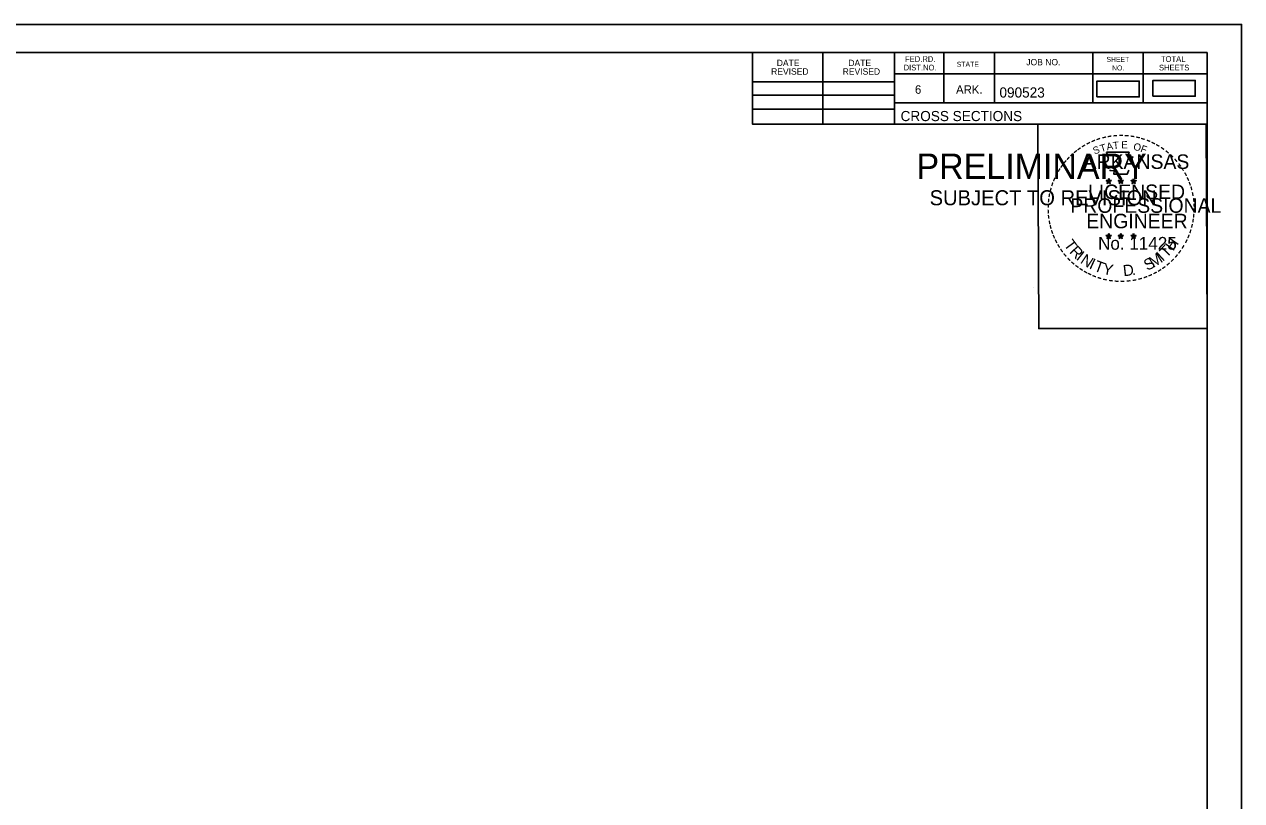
# Model space of a CAD drawing. Extents: x 1406028 to 1412453, y 321733 to 325986.
# Drawn here: x 1412285.4 to 1412453.2, y 322598 to 322705 of the extents above; entities that cross this region are included whole.
import ezdxf

# ---------------------------------------------------------------- set-up
doc = ezdxf.new("R2010")
doc.units = 0
for name, color, linetype in [('R_Alt Surface', 7, 'Continuous'), ('R_Border', 7, 'Continuous'), ('R_Border PE', 7, 'Continuous'), ('R_Border Prem', 7, 'Continuous'), ('R_Fin Surface', 7, 'Continuous'), ('R_No Plot', 7, 'Continuous')]:
    doc.layers.add(name, color=color, linetype=linetype)

msp = doc.modelspace()

# ---------------------------------------------------------------- linework, layer by layer
at = {"layer": 'R_Alt Surface'}
msp.add_lwpolyline([(1412433.22, 322695.04), (1412439.06, 322695.04), (1412439.06, 322697.23), (1412433.22, 322697.23)], close=True, dxfattribs=at)
at = {"layer": 'R_Border'}
for p, q in [((1412132.23, 322701.15), (1412448.41, 322701.15)), ((1412385.77, 322691.27), (1412385.77, 322701.15)), ((1412395.45, 322691.27), (1412395.45, 322701.15)), ((1412405.31, 322701.15), (1412405.31, 322691.27)), ((1412412.15, 322701.15), (1412412.15, 322694.21)), ((1412419.09, 322701.15), (1412419.09, 322694.21)), ((1412432.67, 322701.15), (1412432.67, 322694.21)), ((1412439.61, 322701.15), (1412439.61, 322694.21)), ((1412448.41, 322495.69), (1412448.41, 322701.15)), ((1412448.41, 322698.21), (1412405.31, 322698.21)), ((1412448.41, 322698.23), (1412448.41, 322698.23)), ((1412385.77, 322697.13), (1412405.31, 322697.13)), ((1412385.77, 322695.27), (1412405.31, 322695.27)), ((1412448.41, 322694.21), (1412405.31, 322694.21)), ((1412408.27, 322694.21), (1412448.41, 322694.21)), ((1412385.77, 322693.33), (1412405.31, 322693.33)), ((1412448.41, 322691.27), (1412385.77, 322691.27))]:
    msp.add_line(p, q, dxfattribs=at)
at = {"layer": 'R_Border PE'}
for p, q in [((1412434.5, 322683.52), (1412434.84, 322683.41)), ((1412434.5, 322683.52), (1412434.75, 322683.48)), ((1412434.5, 322683.52), (1412434.73, 322683.4)), ((1412434.63, 322683.11), (1412434.84, 322683.41)), ((1412434.63, 322683.11), (1412434.75, 322683.36)), ((1412434.63, 322683.11), (1412434.84, 322683.33)), ((1412434.84, 322683.77), (1412434.8, 322683.52)), ((1412434.84, 322683.41), (1412434.84, 322683.77)), ((1412434.84, 322683.77), (1412434.89, 322683.52)), ((1412435.19, 322683.52), (1412434.84, 322683.41)), ((1412435.06, 322683.11), (1412434.84, 322683.41)), ((1412435.06, 322683.11), (1412434.84, 322683.33)), ((1412435.19, 322683.52), (1412434.91, 322683.47)), ((1412435.06, 322683.11), (1412434.92, 322683.4)), ((1412435.19, 322683.52), (1412434.99, 322683.42)), ((1412436.17, 322683.52), (1412436.51, 322683.41)), ((1412436.17, 322683.52), (1412436.42, 322683.48)), ((1412436.17, 322683.52), (1412436.4, 322683.4)), ((1412436.3, 322683.11), (1412436.51, 322683.41)), ((1412436.3, 322683.11), (1412436.42, 322683.36)), ((1412436.3, 322683.11), (1412436.51, 322683.33)), ((1412436.51, 322683.77), (1412436.47, 322683.52)), ((1412436.51, 322683.41), (1412436.51, 322683.77)), ((1412436.51, 322683.77), (1412436.56, 322683.52)), ((1412436.86, 322683.52), (1412436.51, 322683.41)), ((1412436.73, 322683.11), (1412436.51, 322683.41)), ((1412436.73, 322683.11), (1412436.51, 322683.33)), ((1412436.86, 322683.52), (1412436.58, 322683.47)), ((1412436.73, 322683.11), (1412436.59, 322683.4)), ((1412436.86, 322683.52), (1412436.66, 322683.42)), ((1412437.93, 322683.51), (1412438.28, 322683.4)), ((1412437.93, 322683.51), (1412438.18, 322683.46)), ((1412437.93, 322683.51), (1412438.17, 322683.39)), ((1412438.06, 322683.1), (1412438.28, 322683.4)), ((1412438.06, 322683.1), (1412438.19, 322683.34)), ((1412438.06, 322683.1), (1412438.28, 322683.32)), ((1412438.28, 322683.76), (1412438.24, 322683.51)), ((1412438.28, 322683.4), (1412438.28, 322683.76)), ((1412438.28, 322683.76), (1412438.33, 322683.51)), ((1412438.63, 322683.51), (1412438.28, 322683.4)), ((1412438.49, 322683.1), (1412438.28, 322683.4)), ((1412438.49, 322683.1), (1412438.28, 322683.31)), ((1412438.63, 322683.51), (1412438.34, 322683.46)), ((1412438.49, 322683.1), (1412438.35, 322683.39)), ((1412438.63, 322683.51), (1412438.42, 322683.41)), ((1412434.49, 322675.95), (1412434.84, 322675.84)), ((1412434.49, 322675.95), (1412434.74, 322675.9)), ((1412434.49, 322675.95), (1412434.73, 322675.83)), ((1412434.62, 322675.54), (1412434.84, 322675.84)), ((1412434.62, 322675.54), (1412434.75, 322675.78)), ((1412434.62, 322675.54), (1412434.84, 322675.76)), ((1412434.84, 322676.2), (1412434.8, 322675.95)), ((1412434.84, 322675.84), (1412434.84, 322676.2)), ((1412434.84, 322676.2), (1412434.89, 322675.95)), ((1412435.19, 322675.95), (1412434.84, 322675.84)), ((1412435.05, 322675.54), (1412434.84, 322675.84)), ((1412435.05, 322675.54), (1412434.84, 322675.75)), ((1412435.19, 322675.95), (1412434.9, 322675.9)), ((1412435.05, 322675.54), (1412434.92, 322675.83)), ((1412435.19, 322675.95), (1412434.98, 322675.85)), ((1412436.16, 322675.95), (1412436.51, 322675.84)), ((1412436.16, 322675.95), (1412436.41, 322675.9)), ((1412436.16, 322675.95), (1412436.4, 322675.83)), ((1412436.29, 322675.54), (1412436.51, 322675.84)), ((1412436.29, 322675.54), (1412436.42, 322675.78)), ((1412436.29, 322675.54), (1412436.51, 322675.76)), ((1412436.51, 322676.2), (1412436.47, 322675.95)), ((1412436.51, 322675.84), (1412436.51, 322676.2)), ((1412436.51, 322676.2), (1412436.56, 322675.95)), ((1412436.86, 322675.95), (1412436.51, 322675.84)), ((1412436.72, 322675.54), (1412436.51, 322675.84)), ((1412436.72, 322675.54), (1412436.51, 322675.75)), ((1412436.86, 322675.95), (1412436.57, 322675.9)), ((1412436.72, 322675.54), (1412436.59, 322675.83)), ((1412436.86, 322675.95), (1412436.65, 322675.85)), ((1412437.93, 322675.94), (1412438.28, 322675.83)), ((1412437.93, 322675.94), (1412438.18, 322675.89)), ((1412437.93, 322675.94), (1412438.16, 322675.82)), ((1412438.06, 322675.53), (1412438.28, 322675.83)), ((1412438.06, 322675.53), (1412438.19, 322675.77)), ((1412438.06, 322675.53), (1412438.27, 322675.75)), ((1412438.28, 322676.19), (1412438.24, 322675.94)), ((1412438.49, 322675.53), (1412438.27, 322675.74)), ((1412438.28, 322675.83), (1412438.28, 322676.19)), ((1412438.28, 322676.19), (1412438.33, 322675.94)), ((1412438.62, 322675.94), (1412438.28, 322675.83)), ((1412438.49, 322675.53), (1412438.28, 322675.83)), ((1412438.62, 322675.94), (1412438.34, 322675.89)), ((1412438.49, 322675.53), (1412438.35, 322675.82)), ((1412438.62, 322675.94), (1412438.42, 322675.84))]:
    msp.add_line(p, q, dxfattribs=at)
for points in [[(1412434.54, 322687.4), (1412434.81, 322686.57)], [(1412438.05, 322686.48), (1412438.19, 322686.76), (1412437.5, 322686.74), (1412437.65, 322687.4), (1412434.54, 322687.4)], [(1412435.03, 322684.98), (1412435.03, 322684.89), (1412435.59, 322684.87), (1412435.54, 322684.4), (1412437.41, 322684.4), (1412437.61, 322684.93)], [(1412434.84, 322683.77), (1412435.06, 322683.11), (1412434.5, 322683.52), (1412435.19, 322683.52), (1412434.63, 322683.11), (1412434.84, 322683.77)], [(1412436.51, 322683.77), (1412436.73, 322683.11), (1412436.17, 322683.52), (1412436.86, 322683.52), (1412436.3, 322683.11), (1412436.51, 322683.77)], [(1412438.28, 322683.76), (1412438.49, 322683.1), (1412437.93, 322683.51), (1412438.63, 322683.51), (1412438.06, 322683.1), (1412438.28, 322683.76)], [(1412434.84, 322676.2), (1412435.05, 322675.54), (1412434.49, 322675.95), (1412435.19, 322675.95), (1412434.62, 322675.54), (1412434.84, 322676.2)], [(1412436.51, 322676.2), (1412436.72, 322675.54), (1412436.16, 322675.95), (1412436.86, 322675.95), (1412436.29, 322675.54), (1412436.51, 322676.2)], [(1412438.28, 322676.19), (1412438.49, 322675.53), (1412437.93, 322675.94), (1412438.62, 322675.94), (1412438.06, 322675.53), (1412438.28, 322676.19)]]:
    msp.add_lwpolyline(points, dxfattribs=at)
for centre, radius in [((1412434.84, 322683.41), 0.172), ((1412434.84, 322683.41), 0.145), ((1412434.84, 322683.41), 0.116), ((1412434.84, 322683.41), 0.0991), ((1412434.84, 322683.41), 0.0747), ((1412434.84, 322683.41), 0.0495), ((1412434.84, 322683.41), 0.0296), ((1412436.51, 322683.41), 0.172), ((1412436.51, 322683.41), 0.145), ((1412436.51, 322683.41), 0.116), ((1412436.51, 322683.41), 0.0991), ((1412436.51, 322683.41), 0.0747), ((1412436.51, 322683.41), 0.0495), ((1412436.51, 322683.41), 0.0296), ((1412438.28, 322683.4), 0.172), ((1412438.28, 322683.4), 0.145), ((1412438.28, 322683.4), 0.116), ((1412438.28, 322683.4), 0.0991), ((1412438.28, 322683.4), 0.0747), ((1412438.28, 322683.4), 0.0495), ((1412438.28, 322683.4), 0.0296), ((1412434.84, 322675.84), 0.172), ((1412434.84, 322675.84), 0.145), ((1412434.84, 322675.84), 0.116), ((1412434.84, 322675.84), 0.0991), ((1412434.84, 322675.84), 0.0747), ((1412434.84, 322675.84), 0.0495), ((1412434.84, 322675.84), 0.0296), ((1412436.51, 322675.84), 0.172), ((1412436.51, 322675.84), 0.145), ((1412436.51, 322675.84), 0.116), ((1412436.51, 322675.84), 0.0991), ((1412436.51, 322675.84), 0.0747), ((1412436.51, 322675.84), 0.0495), ((1412436.51, 322675.84), 0.0296), ((1412438.28, 322675.83), 0.172), ((1412438.28, 322675.83), 0.145), ((1412438.28, 322675.83), 0.116), ((1412438.28, 322675.83), 0.0991), ((1412438.28, 322675.83), 0.0747), ((1412438.28, 322675.83), 0.0495), ((1412438.28, 322675.83), 0.0296)]:
    msp.add_circle(centre, radius, dxfattribs=at)
at = {"layer": 'R_Fin Surface'}
msp.add_lwpolyline([(1412440.94, 322695.13), (1412446.78, 322695.13), (1412446.78, 322697.32), (1412440.94, 322697.32)], close=True, dxfattribs=at)
at = {"layer": 'R_No Plot'}
for p, q in [((1412119.83, 322705.04), (1412453.16, 322705.04)), ((1412424.45, 322668.81), (1412424.45, 322668.81))]:
    msp.add_line(p, q, dxfattribs=at)
for points in [[(1412119.82, 322705.04), (1412453.16, 322705.04), (1412453.16, 322491.7), (1412119.82, 322491.7)], [(1412366.15, 322701.15), (1412385.77, 322701.15), (1412385.77, 322691.27), (1412401.88, 322691.27), (1412425.08, 322691.27), (1412425.2, 322663.11), (1412448.41, 322663.11), (1412448.41, 322495.69), (1412132.23, 322495.69), (1412132.23, 322701.15)], [(1412425.08, 322691.27), (1412448.29, 322691.27), (1412448.41, 322663.11), (1412425.2, 322663.11)]]:
    msp.add_lwpolyline(points, close=True, dxfattribs=at)

# ---------------------------------------------------------------- texts
at = {"layer": 'R_Border'}
for s, height, p in [('DATE', 0.879, (1412389.11, 322699.28)), ('DATE', 0.879, (1412398.97, 322699.28)), ('DIST.NO.', 0.782, (1412406.59, 322698.69)), ('FED.RD.', 0.782, (1412406.79, 322699.87)), ('STATE', 0.684, (1412413.91, 322699.19)), ('JOB NO.', 0.879, (1412423.49, 322699.39)), ('SHEET', 0.684, (1412434.53, 322699.87)), ('NO.', 0.684, (1412435.31, 322698.69)), ('SHEETS', 0.782, (1412441.77, 322698.69)), ('TOTAL', 0.782, (1412442.05, 322699.87)), ('REVISED', 0.879, (1412388.33, 322698.1)), ('REVISED', 0.879, (1412398.19, 322698.1)), ('6', 1.17, (1412408.15, 322695.47)), ('ARK.', 1.172, (1412413.81, 322695.47)), ('090523', 1.4, (1412419.79, 322694.95)), ('CROSS SECTIONS', 1.4, (1412406.17, 322691.7))]:
    msp.add_text(s, height=height, rotation=360, dxfattribs=at).set_placement(p)
at = {"layer": 'R_Border PE'}
for s, height, rotation, p in [('-', 1.6, 24.3072, (1412432.65, 322688.26)), ('-', 1.6, 19.1761, (1412433.28, 322688.53)), ('-', 1.6, 13.6301, (1412434.03, 322688.77)), ('-', 1.6, 10.2193, (1412434.71, 322688.93)), ('-', 1.6, 5.8968, (1412435.44, 322689.04)), ('-', 1.6, 0.1862, (1412436.21, 322689.11)), ('-', 1.6, 357.743, (1412436.94, 322689.1)), ('-', 1.6, 352.1617, (1412437.68, 322689.04)), ('-', 1.6, 347.2049, (1412438.4, 322688.93)), ('-', 1.6, 342.3362, (1412439.03, 322688.77)), ('-', 1.6, 337.8551, (1412439.77, 322688.55)), ('-', 1.6, 38.9507, (1412430.37, 322686.8)), ('-', 1.6, 36.2317, (1412430.84, 322687.17)), ('-', 1.6, 34.0636, (1412431.42, 322687.57)), ('-', 1.6, 28.7918, (1412432.02, 322687.94)), ('S', 1, 21.594, (1412432.89, 322687.08)), ('T', 1, 16.4036, (1412433.81, 322687.41)), ('A', 1, 11.2132, (1412434.63, 322687.66)), ('T', 1, 6.0228, (1412435.48, 322687.82)), ('E', 1, 0.8323, (1412436.59, 322687.93)), ('O', 1, 350.4515, (1412438.19, 322687.72)), ('F', 1, 340.0707, (1412439.14, 322687.5)), ('-', 1.6, 334.1211, (1412440.4, 322688.28)), ('-', 1.6, 329.6409, (1412440.98, 322688)), ('-', 1.6, 325.8627, (1412441.62, 322687.63)), ('-', 1.6, 320.5297, (1412442.23, 322687.21)), ('-', 1.6, 54.2325, (1412428.67, 322684.85)), ('-', 1.6, 50.6142, (1412429.08, 322685.42)), ('-', 1.6, 48.423, (1412429.49, 322685.9)), ('-', 1.6, 42.9622, (1412429.93, 322686.38)), ('ARKANSAS', 2, 360, (1412431.39, 322685.11)), ('-', 1.6, 315.5786, (1412442.83, 322686.72)), ('-', 1.6, 309.8797, (1412443.4, 322686.17)), ('-', 1.6, 306.6522, (1412443.93, 322685.57)), ('-', 1.6, 62.8713, (1412428.03, 322683.71)), ('-', 1.6, 58.0706, (1412428.34, 322684.32)), ('-', 1.4, 303.6753, (1412444.41, 322685)), ('-', 1.6, 299.6684, (1412444.73, 322684.39)), ('-', 1.6, 294.6628, (1412445.05, 322683.78)), ('-', 1.6, 75.461, (1412427.36, 322681.75)), ('-', 1.6, 72.3945, (1412427.55, 322682.47)), ('-', 1.6, 67.7743, (1412427.77, 322683.1)), ('LICENSED', 2, 360, (1412431.99, 322680.96)), ('DWB', 0.01, 360, (1412434.83, 322683.4)), ('DWB', 0.01, 360, (1412436.5, 322683.4)), ('DWB', 0.01, 360, (1412438.27, 322683.39)), ('-', 1.6, 290.5728, (1412445.31, 322683.2)), ('-', 1.6, 285.1233, (1412445.55, 322682.62)), ('-', 1.6, 85.1863, (1412427.15, 322680.35)), ('-', 1.6, 81.2013, (1412427.22, 322681.04)), ('PROFESSIONAL', 2, 360, (1412429.56, 322679.06)), ('-', 1.6, 280.5493, (1412445.75, 322681.88)), ('-', 1.6, 276.5962, (1412445.91, 322681.11)), ('-', 1.6, 94.1959, (1412427.16, 322678.92)), ('-', 1.6, 89.0622, (1412427.12, 322679.65)), ('ENGINEER', 2, 360, (1412431.75, 322676.93)), ('-', 1.6, 263.5172, (1412445.98, 322679.09)), ('-', 1.6, 274.3301, (1412445.97, 322680.39)), ('-', 1.6, 269.9407, (1412446, 322679.76)), ('-', 1.6, 98.9479, (1412427.23, 322678.26)), ('-', 1.6, 101.7149, (1412427.37, 322677.52)), ('-', 1.6, 105.4578, (1412427.53, 322676.93)), ('-', 1.6, 255.7626, (1412445.8, 322677.76)), ('-', 1.6, 260.9953, (1412445.91, 322678.44)), ('-', 1.6, 109.0874, (1412427.74, 322676.3)), ('-', 1.6, 114.0643, (1412428, 322675.7)), ('No. 11425', 1.757, 360, (1412433.38, 322673.98)), ('DWB', 0.01, 360, (1412434.83, 322675.83)), ('DWB', 0.01, 360, (1412436.5, 322675.83)), ('DWB', 0.01, 360, (1412438.26, 322675.82)), ('H', 1.54, 54.6088, (1412443.72, 322673.71)), ('-', 1.6, 247.8887, (1412445.4, 322676.37)), ('-', 1.6, 252.8681, (1412445.62, 322677.04)), ('-', 1.6, 115.7289, (1412428.3, 322675.08)), ('-', 1.6, 120.4471, (1412428.66, 322674.5)), ('-', 1.6, 125.8934, (1412429.06, 322673.94)), ('T', 1.54, 306.0406, (1412428.6, 322674.67)), ('R', 1.54, 314.005, (1412429.36, 322673.63)), ('T', 1.54, 46.6444, (1412442.83, 322672.77)), ('-', 1.6, 233.8452, (1412444.34, 322674.34)), ('-', 1.6, 239.0712, (1412444.74, 322674.99)), ('-', 1.6, 244.6197, (1412445.14, 322675.74)), ('-', 1.6, 130.7181, (1412429.52, 322673.38)), ('-', 1.6, 134.2238, (1412430.04, 322672.84)), ('-', 1.6, 138.9338, (1412430.57, 322672.37)), ('I', 1.54, 321.9694, (1412430.26, 322672.69)), ('N', 1.54, 326.5002, (1412430.83, 322672.22)), ('I', 1.54, 335.3603, (1412432.04, 322671.44)), ('T', 1.54, 339.8912, (1412432.7, 322671.11)), ('S', 1.54, 26.9312, (1412440.15, 322671.04)), ('M', 1.54, 32.6563, (1412440.99, 322671.44)), ('I', 1.54, 42.1136, (1412442.27, 322672.29)), ('-', 1.6, 221.0851, (1412442.91, 322672.7)), ('-', 1.6, 225.7653, (1412443.43, 322673.21)), ('-', 1.6, 231.2538, (1412443.91, 322673.77)), ('-', 1.6, 144.6463, (1412431.12, 322671.97)), ('-', 1.6, 148.0898, (1412431.68, 322671.6)), ('-', 1.6, 151.5704, (1412432.26, 322671.27)), ('-', 1.6, 154.6002, (1412432.78, 322671.03)), ('Y', 1.54, 347.8556, (1412433.92, 322670.66)), ('D', 1.54, 6.3969, (1412436.9, 322670.31)), ('.', 1.54, 13.7642, (1412438.09, 322670.43)), ('-', 1.6, 204.2516, (1412440.64, 322671.17)), ('-', 1.6, 207.3568, (1412441.27, 322671.49)), ('-', 1.6, 212.2491, (1412441.83, 322671.84)), ('-', 1.6, 215.7363, (1412442.36, 322672.22)), ('-', 1.6, 158.5612, (1412433.41, 322670.77)), ('-', 1.6, 162.7983, (1412434.09, 322670.56)), ('-', 1.6, 167.5555, (1412434.81, 322670.39)), ('-', 1.6, 173.1155, (1412435.58, 322670.28)), ('-', 1.6, 176.5183, (1412436.33, 322670.23)), ('-', 1.6, 181.5918, (1412437.07, 322670.25)), ('-', 1.6, 185.8167, (1412437.88, 322670.33)), ('-', 1.6, 191.2858, (1412438.62, 322670.46)), ('-', 1.6, 195.4743, (1412439.35, 322670.66)), ('-', 1.6, 200.7184, (1412440.02, 322670.9))]:
    msp.add_text(s, height=height, rotation=rotation, dxfattribs=at).set_placement(p)
at = {"layer": 'R_Border Prem'}
for s, height, p in [('PRELIMINARY', 3.5, (1412408.36, 322683.73)), ('DWB', 0.01, (1412409.11, 322685.58)), ('SUBJECT TO REVISION', 2.0751, (1412410.17, 322680.1))]:
    msp.add_text(s, height=height, rotation=360, dxfattribs=at).set_placement(p)

doc.saveas('drawing.dxf')
